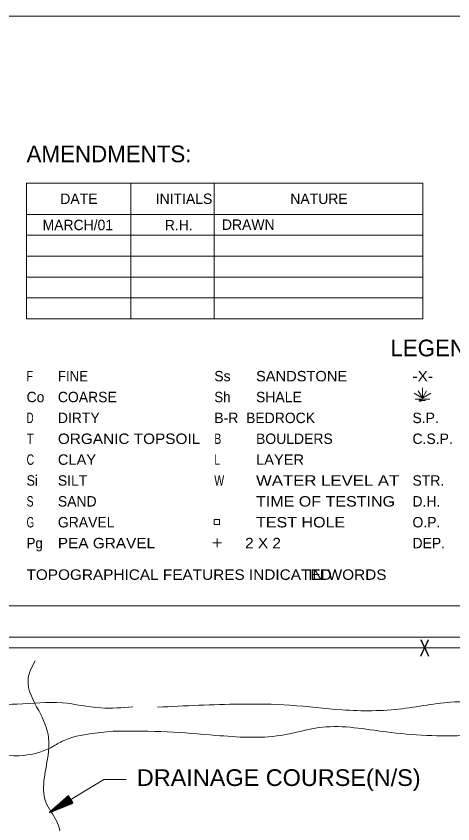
# Model space of a CAD drawing. Extents: x -496 to 480, y -450 to 700.
# Drawn here: x 5 to 214.3, y 312.9 to 700 of the extents above; entities that cross this region are included whole.
import ezdxf
from ezdxf.enums import TextEntityAlignment as Align

# ---------------------------------------------------------------- set-up
doc = ezdxf.new("R2010")
doc.units = 0
doc.header["$LTSCALE"] = 2
doc.header["$PDMODE"] = 32
doc.header["$PDSIZE"] = 1
for name, color, linetype, lineweight in [('1', 7, 'Continuous', 13), ('3', 7, 'Continuous', 13), ('4', 7, 'Continuous', 25)]:
    doc.layers.add(name, color=color, linetype=linetype, lineweight=lineweight)

msp = doc.modelspace()

# ---------------------------------------------------------------- linework, layer by layer
at = {"layer": '1'}
for p, q in [((199.983, 619.973), (9.983, 619.973)), ((9.983, 619.973), (9.983, 554.973)), ((59.983, 619.973), (59.983, 554.973)), ((99.983, 619.973), (99.983, 554.973)), ((199.983, 554.973), (199.983, 619.973)), ((9.983, 604.973), (199.983, 604.973)), ((9.983, 594.973), (199.983, 594.973)), ((9.983, 584.973), (199.983, 584.973)), ((9.983, 574.973), (199.983, 574.973)), ((9.983, 564.973), (199.983, 564.973)), ((199.76, 516.875), (195.76, 519.375)), ((199.76, 516.875), (197.76, 520.375)), ((199.76, 516.875), (199.76, 521.875)), ((199.76, 516.875), (201.76, 520.375)), ((199.76, 516.875), (203.76, 519.375)), ((196.26, 516.375), (203.26, 516.375)), ((198.26, 515.875), (201.26, 515.875)), ((101.291, 449.597), (101.291, 445.597)), ((103.353, 447.618), (99.353, 447.618))]:
    msp.add_line(p, q, dxfattribs=at)
for points in [[(449.983, -450.027), (449.983, 399.973), (449.983, 699.973), (-450.017, 699.973), (-450.017, 49.973), (-450.017, -450.027)], [(9.983, 554.973), (99.983, 554.973), (199.983, 554.973)], [(402.281, -402.333), (402.281, 402.339), (-402.391, 402.339)]]:
    msp.add_lwpolyline(points, dxfattribs=at)
msp.add_lwpolyline([(99.967, 456.301), (99.967, 458.832), (102.499, 458.832), (102.499, 456.301)], close=True, dxfattribs=at)
msp.add_point((198.76, 515.875), dxfattribs=at)
at = {"layer": '3'}
msp.add_line((402.281, 417.339), (-402.391, 417.339), dxfattribs=at)
msp.add_lwpolyline([(410.562, 397.339), (-397.391, 397.339), (-397.391, 23.005)], dxfattribs=at)
for points in [[(14.079, 391.089), (10.669, 381.892), (15.784, 367.246), (20.558, 354.303), (18.512, 335.229), (19.194, 323.308), (24.309, 314.452), (26.006, 294.553)], [(-360.928, 32.503), (-364.618, 32.503), (-370.152, 36.803), (-366.462, 52.771), (-367.077, 89.622), (-367.692, 111.733), (-367.692, 129.544), (-365.233, 204.474), (-367.692, 222.9), (-367.692, 241.939), (-367.692, 275.719), (-367.692, 294.145), (-370.152, 319.326), (-368.307, 346.964), (-367.077, 354.949), (-364.003, 361.705), (-358.469, 367.232), (-350.475, 372.146), (-328.339, 369.075), (-249.018, 367.232), (-212.739, 369.075), (-184.454, 370.303), (-156.784, 369.075), (-126.039, 369.689), (-110.052, 371.532), (-86.686, 369.689), (-25.196, 366.618), (-14.128, 369.075), (5.548, 370.303), (27.07, 370.918), (45.517, 368.461), (60.889, 369.075)], [(72.753, 368.814), (112.359, 370.322), (136.242, 369.767), (161.235, 367.548), (190.117, 368.102), (216.777, 371.431), (239.549, 369.212), (261.766, 366.438), (287.87, 368.102), (311.198, 370.322), (333.97, 369.767), (358.408, 368.657), (378.958, 366.993), (391.733, 369.212), (400.619, 368.102)], [(-360.928, 32.503), (-354.165, 42.33), (-351.09, 51.543), (-352.935, 81.024), (-355.394, 107.433), (-352.32, 127.087), (-351.09, 165.167), (-353.55, 187.891), (-353.55, 218.6), (-356.009, 235.798), (-352.32, 258.522), (-350.475, 281.861), (-352.32, 308.271), (-354.165, 323.011), (-355.394, 336.523), (-355.394, 346.964), (-351.705, 352.492), (-338.792, 357.406), (-308.048, 357.406), (-285.911, 359.862), (-274.228, 356.791), (-261.93, 352.492), (-249.018, 349.421), (-239.179, 350.65), (-224.422, 355.563), (-221.347, 356.177), (-209.664, 351.264), (-194.292, 346.964), (-171.541, 347.579), (-160.473, 350.65), (-154.939, 353.72), (-145.101, 357.406), (-140.796, 358.634), (-130.958, 358.634), (-102.673, 358.02), (-94.064, 356.791), (-86.686, 353.72), (-69.469, 350.035), (-56.556, 344.508), (-35.035, 344.508), (-21.507, 347.579), (-10.439, 346.964), (8.623, 345.736), (21.536, 349.421), (27.07, 352.492), (41.212, 356.177), (52.895, 357.406)], [(52.895, 357.406), (77.367, 357.007), (100.695, 355.343), (131.798, 355.343), (151.793, 359.226), (182.341, 357.007), (221.22, 355.343), (242.881, 357.007), (258.433, 358.117), (290.647, 357.007), (302.311, 354.788), (346.744, 356.452), (358.963, 358.117), (373.96, 358.117), (387.845, 357.007), (401.175, 357.562)]]:
    msp.add_spline(points, degree=3, dxfattribs=at)
at = {"layer": '4', "lineweight": 13}
msp.add_lwpolyline([(57.791, 334.255), (46.987, 334.255), (20.932, 318.386)], dxfattribs=at)
at = {"layer": '4'}
msp.add_lwpolyline([(20.932, 318.386), (32.222, 322.92), (30.141, 326.336)], close=True, dxfattribs=at)
msp.add_lwpolyline([(32.076, 322.97), (21.423, 318.684), (30.087, 326.111), (31.948, 323.096), (22.052, 319.067), (30.01, 325.864), (31.724, 323.135), (22.717, 319.472), (29.957, 325.577), (31.501, 323.252), (23.483, 319.914), (29.855, 325.286), (31.202, 323.324), (24.401, 320.446), (29.823, 324.963), (30.883, 323.434), (25.389, 321.024), (29.753, 324.541), (30.538, 323.501), (26.495, 321.621), (29.593, 324.14), (30.126, 323.554), (27.758, 322.415), (29.451, 323.625)], dxfattribs=at)

# ---------------------------------------------------------------- texts
at = {"layer": '1'}
for s, height, p in [('AMENDMENTS:', 8, (9.983, 629.973)), ('Ss', 5, (99.983, 524.973)), ('Co', 5, (9.983, 514.973)), ('COARSE', 5, (24.983, 514.973)), ('SHALE', 5, (119.983, 514.973)), ('DIRTY', 5, (24.983, 504.973)), ('B-R  BEDROCK', 5, (99.983, 504.973)), ('S.P.', 5, (194.983, 504.973)), ('BOULDERS', 5, (119.983, 494.973)), ('C.S.P.', 5, (194.983, 494.973)), ('SILT', 5, (24.983, 474.973)), ('STR.', 5, (194.983, 474.973)), ('SAND', 5, (24.983, 464.973)), ('D.H.', 5, (194.983, 464.973)), ('GRAVEL', 5, (24.983, 454.973)), ('O.P.', 5, (194.983, 454.973)), ('DEP.', 5, (194.983, 444.973))]:
    msp.add_text(s, height=height, dxfattribs=at).set_placement(p)
for s, height, p in [('DATE', 5, (35.081, 609.973)), ('INITIALS', 5, (85.453, 609.973)), ('NATURE', 5, (150.16, 609.973)), ('MARCH/01', 5, (34.552, 597.405)), ('R.H.', 5, (82.941, 597.343)), ('DRAWN', 5, (116.266, 597.567)), ('LEGEND', 8, (206.378, 536.973))]:
    msp.add_text(s, height=height, dxfattribs=at).set_placement(p, align=Align.CENTER)
for s, width, p in [('F', 0.75, (9.983, 524.973)), ('FINE', 0.95, (24.983, 524.973)), ('SANDSTONE', 1.05, (119.983, 524.973)), ('-X-', 1.1, (194.983, 524.973)), ('Sh', 0.95, (99.983, 514.973)), ('D', 0.7, (9.983, 504.973)), ('T', 0.85, (9.983, 494.973)), ('ORGANIC TOPSOIL', 1.1, (24.983, 494.973)), ('B', 0.75, (99.983, 494.973)), ('C', 0.75, (9.983, 484.973)), ('CLAY', 1.05, (24.983, 484.973)), ('L', 0.75, (99.983, 484.973)), ('LAYER', 1.05, (119.983, 484.973)), ('Si', 0.9, (9.983, 474.973)), ('W', 0.75, (99.983, 474.973)), ('WATER LEVEL AT', 1.2, (119.983, 474.973)), ('S', 0.75, (9.983, 464.973)), ('TIME OF TESTING', 1.15, (119.983, 464.973)), ('G', 0.7, (9.983, 454.973)), ('TEST HOLE', 1.15, (119.983, 454.973)), ('Pg', 0.95, (9.983, 444.973)), ('PEA GRAVEL', 1.1, (24.983, 444.973)), ('   2 X 2', 1.1, (108.608, 444.973)), ('TOPOGRAPHICAL FEATURES INDICATED', 1.1, (9.942, 429.855)), ('IN WORDS', 1.1, (144.942, 429.855))]:
    msp.add_text(s, height=5, dxfattribs=dict(at, width=width)).set_placement(p)
at = {"layer": '3', "width": 0.7}
msp.add_text('X', height=8, dxfattribs=at).set_placement((200.809, 393.191), align=Align.CENTER)
at = {"layer": '4', "width": 1.05}
msp.add_text('DRAINAGE COURSE(N/S)', height=8, dxfattribs=at).set_placement((130.872, 331.081), align=Align.CENTER)

doc.saveas('drawing.dxf')
